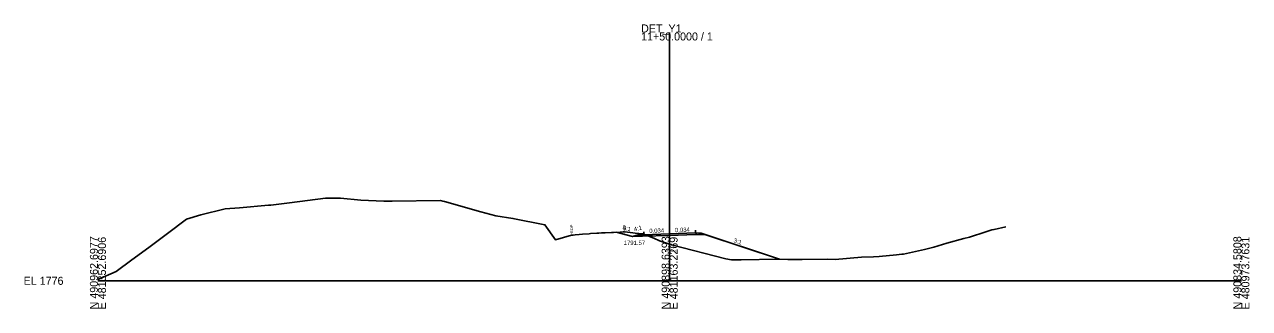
# Model space of a CAD drawing. Extents: x -26 to 403, y -10 to 3149.
# Drawn here: x -25.7 to 402.8, y 1490.3 to 1589.7 of the extents above; entities that cross this region are included whole.
import ezdxf

# ---------------------------------------------------------------- set-up
doc = ezdxf.new("R2010")
doc.units = 0
for name, color, linetype in [('Exist Cross Section Cell', 7, 'Continuous'), ('Exist XS Center Line Elevation Label', 7, 'Continuous'), ('Exist XS Ground Line', 7, 'Continuous'), ('Prop XS Ditch Slope Text', 7, 'Continuous'), ('Prop XS Ditch Standard Text', 7, 'Continuous'), ('Prop XS Dump Level', 7, 'Continuous'), ('Prop XS EOT Tick Mark', 7, 'Continuous'), ('Prop XS Finish Grade', 7, 'Continuous'), ('Prop XS Finish Grade Earthwork', 7, 'Continuous'), ('Prop XS Finish Grade Pavement', 7, 'Continuous'), ('Prop XS Pvmt Edge Slope', 7, 'Continuous'), ('Prop XS SE Text', 7, 'Continuous'), ('Prop XS Side Slope Text', 7, 'Continuous'), ('Prop XS Subgrade Earthwork', 7, 'Continuous'), ('Scratch_Level_3', 7, 'Continuous'), ('Scratch_Level_4', 7, 'Continuous')]:
    doc.layers.add(name, color=color, linetype=linetype)

msp = doc.modelspace()

# ---------------------------------------------------------------- linework, layer by layer
at = {"layer": 'Exist Cross Section Cell'}
for p, q in [((200, 1500), (200, 1586.95)), ((0, 1500), (200, 1500)), ((200, 1500), (400, 1500))]:
    msp.add_line(p, q, dxfattribs=at)
at = {"layer": 'Exist XS Ground Line'}
msp.add_lwpolyline([(0, 1500.5), (6.34, 1503.24), (11.86, 1507.39), (17.85, 1511.64), (24.37, 1516.53), (30.94, 1521.54), (35.95, 1523.16), (44.49, 1525.19), (49.53, 1525.52), (59.71, 1526.46), (60.11, 1526.5), (60.45, 1526.54), (66.99, 1527.3), (79.62, 1528.98), (84.81, 1528.94), (92.02, 1528.29), (100.06, 1527.9), (102.92, 1527.89), (119.82, 1528.17), (120.63, 1527.94), (121.28, 1527.8), (133.97, 1524.18), (139.17, 1522.71), (145.14, 1521.86), (156.37, 1519.61), (160.01, 1514.4), (165.71, 1515.97), (166.19, 1516.02), (166.94, 1516.09), (168.35, 1516.21), (169.55, 1516.32), (171.85, 1516.5), (172.27, 1516.53), (174.57, 1516.68), (175.27, 1516.72), (176.16, 1516.76), (177.45, 1516.82), (179.63, 1516.94), (180.3, 1516.97), (182.67, 1517.07), (183.88, 1517.11), (184.23, 1517.12), (185.24, 1517.01), (187.07, 1516.81), (187.95, 1516.72), (190.6, 1516.47), (194.44, 1514.93), (196.41, 1514.04), (200, 1512.81), (200.7, 1512.57), (219.61, 1507.73), (221.67, 1507.37), (223.77, 1507.38), (225, 1507.33), (237.75, 1507.57), (241.37, 1507.49), (246.41, 1507.45), (255.13, 1507.53), (257.94, 1507.51), (267.08, 1508.24), (271.25, 1508.43), (273.31, 1508.54), (279.41, 1509.11), (281.2, 1509.28), (281.8, 1509.37), (289.09, 1510.97), (292.36, 1511.8), (296.98, 1513.15), (302.92, 1514.79), (304.87, 1515.33), (310.63, 1517.14), (312.76, 1517.81), (313.48, 1517.99), (317.58, 1518.93)], dxfattribs=at)
at = {"layer": 'Prop XS Dump Level'}
for p, q in [((191, 1516.15), (200, 1516.46)), ((200, 1516.46), (209, 1516.77))]:
    msp.add_line(p, q, dxfattribs=at)
at = {"layer": 'Prop XS EOT Tick Mark'}
for p, q in [((191, 1516.15), (191, 1517.15)), ((209, 1516.77), (209, 1517.77))]:
    msp.add_line(p, q, dxfattribs=at)
at = {"layer": 'Prop XS Finish Grade'}
for p, q in [((189, 1516.07), (187, 1515.57)), ((191, 1516.15), (189, 1516.07)), ((209, 1516.77), (211, 1516.69)), ((211, 1516.69), (212.67, 1516.13))]:
    msp.add_line(p, q, dxfattribs=at)
at = {"layer": 'Prop XS Finish Grade Earthwork'}
for p, q in [((187, 1515.57), (181.24, 1517.01)), ((212.67, 1516.13), (238.38, 1507.56))]:
    msp.add_line(p, q, dxfattribs=at)
at = {"layer": 'Prop XS Finish Grade Pavement'}
for p, q in [((191, 1516.15), (200, 1516.46)), ((200, 1516.46), (209, 1516.77))]:
    msp.add_line(p, q, dxfattribs=at)
at = {"layer": 'Prop XS Pvmt Edge Slope'}
for p, q in [((191, 1516.15), (190.44, 1515.59)), ((209, 1516.77), (209.56, 1516.21))]:
    msp.add_line(p, q, dxfattribs=at)
at = {"layer": 'Prop XS Subgrade Earthwork'}
for p, q in [((190.44, 1515.59), (187, 1515.57)), ((200, 1515.92), (190.44, 1515.59)), ((209, 1516.22), (200, 1515.92)), ((209, 1516.22), (212.67, 1516.13))]:
    msp.add_line(p, q, dxfattribs=at)
at = {"layer": 'Scratch_Level_4'}
for p, q in [((187, 1515.57), (181.24, 1517.01)), ((189, 1516.07), (187, 1515.57)), ((189, 1516.07), (189.91, 1516.11)), ((191, 1516.15), (189.91, 1516.11)), ((191, 1516.15), (200, 1516.46)), ((200, 1516.46), (209, 1516.77)), ((209, 1516.77), (210.07, 1516.72)), ((210.07, 1516.72), (211, 1516.69)), ((211, 1516.69), (238.38, 1507.56))]:
    msp.add_line(p, q, dxfattribs=at)

# ---------------------------------------------------------------- texts
at = {"layer": 'Exist Cross Section Cell'}
for s, p in [('11+50.0000 / 1', (190, 1584.15)), ('DET_Y1', (190, 1586.95)), ('EL 1776', (-26, 1498.6))]:
    msp.add_text(s, height=2.8, dxfattribs=at).set_placement(p)
for s, p in [('N 490962.6977', (0, 1490)), ('E 481352.6906', (2.8, 1490)), ('N 490898.6393', (200, 1490)), ('E 481163.2269', (202.8, 1490)), ('N 490834.5808', (400, 1490)), ('E 480973.7631', (402.8, 1490))]:
    msp.add_text(s, height=2.8, rotation=90, dxfattribs=at).set_placement(p)
at = {"layer": 'Exist XS Center Line Elevation Label'}
msp.add_text('1788.81', height=0.75, dxfattribs=at).set_placement((198.43, 1510.06))
at = {"layer": 'Prop XS Ditch Slope Text'}
msp.add_text('4:1', height=1.5, rotation=14.0362, dxfattribs=at).set_placement((187.64, 1517.28))
at = {"layer": 'Prop XS Ditch Standard Text'}
msp.add_text('1791.57', height=1.5, dxfattribs=at).set_placement((183.92, 1512.57))
at = {"layer": 'Prop XS SE Text'}
for p in [(192.89, 1516.72), (201.89, 1517.02)]:
    msp.add_text('0.034', height=1.5, rotation=1.9516, dxfattribs=at).set_placement(p)
at = {"layer": 'Prop XS Side Slope Text'}
for s, rotation, p in [('4:1', 345.9638, (183.45, 1518)), ('3:1', 341.5651, (222.25, 1513.54))]:
    msp.add_text(s, height=1.5, rotation=rotation, dxfattribs=at).set_placement(p)
at = {"layer": 'Scratch_Level_3'}
for p in [(166.21, 1516.31), (184.73, 1516.27)]:
    msp.add_text('-EOP', height=1, rotation=90, dxfattribs=at).set_placement(p)

doc.saveas('drawing.dxf')
